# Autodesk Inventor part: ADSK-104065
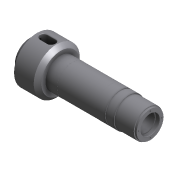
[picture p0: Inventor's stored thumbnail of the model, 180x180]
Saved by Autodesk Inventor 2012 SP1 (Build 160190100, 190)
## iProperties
Shininess: 0.0
Created: 2000-04
Part Number: ADSK-104065
Document SubType Name: Modeling
Stock Number: ADSK-104065
Density: 1 g/cm^3
Material: Default
Density: 0.0
Volumn: 0.0
Area: 0.0
PropertySet Name: Model Information
Control State: 0
Checked Out: False
Master: False
Author: gao
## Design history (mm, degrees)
node "Revolution1" dims "d12" = 360 deg
  sketch "Sketch1"
    geometry: L1 (-29.126, 12.667)-(-29.126, 34.892); L2 (-28.314, -15.908)-(41.343, -15.908); L3 (368.283, 28.542)-(368.283, 12.667); L4 (-29.126, 12.667)-(-29.126, 34.892); L5 (-29.126, 34.892)-(-5.25, 34.892); L6 (-5.25, 34.892)-(-5.25, 60.292) reference; L7 (72.423, 41.242)-(72.423, 60.292); L8 (72.423, 60.292)-(-5.25, 60.292); L9 (-29.126, 12.667)-(368.283, 12.667); L10 (110.523, 34.098)-(110.523, 33.921); L11 (110.523, 33.921)-(238.133, 33.921); L12 (238.133, 33.921)-(238.133, 34.098); L13 (298.433, 34.098)-(298.433, 31.717); L14 (72.423, 34.098)-(110.523, 34.098); L15 (298.433, 31.717)-(361.933, 31.717); L16 (72.423, 34.098)-(72.423, 41.242); L17 (72.423, 60.292)-(72.423, 41.242); L18 (72.423, 60.292)-(72.423, 41.242); L19 (72.423, 60.292)-(72.423, 41.242); L20 (72.423, 41.242)-(72.423, 41.242); L21 (361.933, 31.717)-(361.933, 31.717); L22 (361.933, 31.717)-(361.933, 28.542); L23 (361.933, 28.542)-(368.283, 28.542); L24 (273.033, 34.098)-(273.033, 32.342); L25 (273.033, 32.342)-(269.883, 32.342); L26 (269.883, 32.342)-(269.883, 34.098); L27 (238.133, 34.098)-(269.883, 34.098); L28 (273.033, 34.098)-(298.433, 34.098)
    constraints: 56 end point, 23 perpendicular, 7 parallel, 3 collinear, 2 vertical
    dimensions: "d22" = 23.876 distance of L1.end L5.end; "d23" = 50.8 distance between parallel lines of L2 L5; "d24" = 76.2 distance between parallel lines of L2 L8; "d25" = 77.6732 distance of L7.end L6.end; "d50" = 0.1778 distance between parallel lines of L11 L14; "d51" = 50.00625 distance between parallel lines of L2 L14; "d55" = 28.575 distance between parallel lines of L2 L9; "d62" = 47.625 distance between parallel lines of L2 L15; "d75" = 0 distance of L7.start L16.end; "d76" = 57.15 distance between parallel lines of L2 L20; "d78" = 63.5 distance of L13.end L15.end; "d103" = 38.1 horizontal distance of L10.end L14.start; "d152" = 6.35 distance of L22.end L3.start; "d153" = 44.45 distance between parallel lines of L2 L23; "d156" = 197.4596 horizontal distance of L7.end L26.end; "d157" = 3.15 distance between parallel lines of L26 L24; "d158" = 48.25 distance between parallel lines of L2 L25; "d195" = 31.75 distance of L12.end L26.end; "d196" = 25.4 distance of L24.start L13.start
node "Hole3" dims "d66" = 7.7978, "d67" = 15.875, "d68" = 9.525, "d69" = 60 deg, "d70" = 38.1, "d71" = 118 deg, "d197" = 25.4
  sketch "Sketch4" dims "d64" = 123.825
    geometry: C1 r 50.8 at (0, 0) reference; C2 r 28.575 at (0, 0) reference; 2 further points
    constraints: 1 coincident, 1 vertical alignment, 2 other
    dimensions: "d65" = 0 horizontal distance of C1.centre point (0, 61.913)
node "Circular Pattern2" dims "d72" = 80, "d74" = 45 deg
workplane "Work Plane2"
node "Sketch7"
workplane "Work Plane4"
node "Chamfer3" dims "d154" = 12.7, "d155" = 12.7, "d200" = 45 deg
workplane "Work Plane5"
node "Extrusion3" dims "d163" = 25.4, "d164" = 0
  sketch "Sketch15"
    geometry: L1 (-8.797, -12.684)-(16.603, -12.7); L2 (-8.78, 12.716)-(16.62, 12.7); L3 (38.837, 76.2)-(38.837, -76.2) reference; A1 r 12.7 centre (16.612, 0) between (16.603, -12.7) and (16.62, 12.7); A2 r 12.7 centre (-8.788, 0.016) between (-8.78, 12.716) and (-8.797, -12.684)
    constraints: 4 end point, 4 point on circle, 4 tangent, 2 centre point
    dimensions: "d159" = 25.4 diameter of A1; "d160" = 25.4 diameter of A2 (= d159); "d161" = 22.225 distance from line of A1.centre L3; "d162" = 25.4 distance of A1.centre A2.centre
node "Fillet2" dims "d165" = 1.524
node "Chamfer4" dims "d166" = 1.016, "d167" = 1.016, "d201" = 45 deg
node "Extrusion4" dims "d169" = 12.7, "d170" = 0
  sketch "Sketch16"
    geometry: C1 r 28.575 at (0, 0) reference; C2 r 49.784 at (0, 0) reference; C3 r 31.75 at (0, 0)
    constraints: 1 centre point, 1 coincident
    dimensions: "d168" = 63.5 diameter of C3
node "Hole11" dims "d172" = 3.683, "d173" = 9.525, "d174" = 6.35, "d175" = 60 deg, "d176" = 19.05, "d177" = 118 deg, "d198" = 12.7
  sketch "Sketch17" dims "d171" = 76.2
    geometry: C1 r 49.784 at (0, 0) reference; 2 further points
    constraints: 1 coincident, 1 vertical alignment, 2 other
node "Circular Pattern4" dims "d178" = 60, "d180" = 60 deg
node "Extrusion5" dims "d182" = 12.7, "d183" = 0
  sketch "Sketch18"
    geometry: C1 r 28.575 at (0, 0) reference; C2 r 44.45 at (0, 0) reference; C3 r 31.75 at (0, 0)
    constraints: 1 centre point, 1 coincident
    dimensions: "d181" = 63.5 diameter of C3
node "Hole12" dims "d185" = 3.683, "d186" = 9.525, "d187" = 6.35, "d188" = 60 deg, "d189" = 19.05, "d190" = 118 deg, "d199" = 12.7
  sketch "Sketch19" dims "d184" = 76.2
    geometry: C1 r 44.45 at (0, 0) reference; 2 further points
    constraints: 1 coincident, 1 vertical alignment, 2 other
node "Circular Pattern5" dims "d191" = 40, "d193" = 90 deg
body "Solid1"
other parameters: "d4" = 50.00625, "d16" = 50.00625, "d61" = 50.00625, "d77" = 47.625
